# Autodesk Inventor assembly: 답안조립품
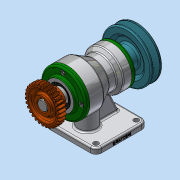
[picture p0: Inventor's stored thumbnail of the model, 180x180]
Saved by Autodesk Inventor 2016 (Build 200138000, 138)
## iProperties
Created: 2019-01
Part Number: 답안조립품
Material: 일반
Document SubType Name: Assembly
Designer: Administrator
Author: Administrator
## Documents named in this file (15)
- C:\Users\Administrator\Desktop\490107V1034\답안조립품.iam
- C:\Users\Administrator\Desktop\490107V1034\본체.ipt
- C:\Users\Administrator\Desktop\490107V1034\축.ipt
- C:\Users\Administrator\Desktop\490107V1034\베어링 6205.ipt
- C:\Users\Administrator\Desktop\490107V1034\베어링 6203.ipt
- C:\Users\Administrator\Desktop\490107V1034\뒤커버.ipt
- C:\Users\Administrator\Desktop\490107V1034\앞커버.ipt
- C:\Users\Administrator\Desktop\490107V1034\오일 실 17 30 8.ipt
- C:\Users\Administrator\Desktop\490107V1034\오일 실 25 38 8.ipt
- C:\Users\Administrator\Desktop\490107V1034\볼트 M4.ipt
- C:\Users\Administrator\Desktop\490107V1034\키 6 x 6 x 18.ipt
- C:\Users\Administrator\Desktop\490107V1034\스퍼기어.ipt
- C:\Users\Administrator\Desktop\490107V1034\멈춤나사 M3.ipt
- C:\Users\Administrator\Desktop\490107V1034\키 5 x 5 x 20.ipt
- C:\Users\Administrator\Desktop\490107V1034\V-벨트풀리.ipt
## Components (1 placed, 1 different names)
1. V-벨트풀리:1
